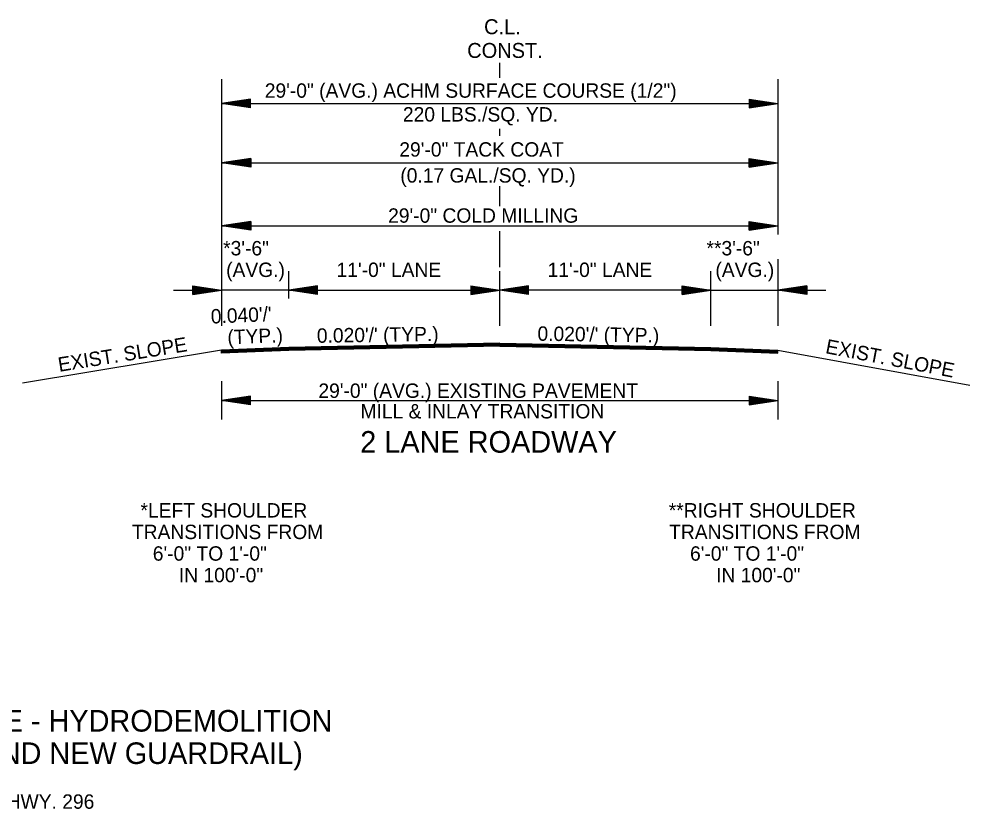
# Model space of a CAD drawing. Extents: x 542112 to 1930787, y -1968972 to 596640.
# Drawn here: x 544741.8 to 545237.5, y -1962582 to -1962170.3 of the extents above; entities that cross this region are included whole.
import ezdxf

# ---------------------------------------------------------------- set-up
doc = ezdxf.new("R2010")
doc.units = 0
doc.layers.add('R_Draft', color=7, linetype='Continuous')

msp = doc.modelspace()

# ---------------------------------------------------------------- linework, layer by layer
at = {"layer": 'R_Draft'}
for p, q in [((544992.39, -1962200.98), (544992.39, -1962193.12)), ((544847.39, -1962201.56), (544847.39, -1962330.24)), ((545137.39, -1962201.56), (545137.39, -1962282.57)), ((544862.39, -1962212.07), (544847.39, -1962214.32)), ((544847.39, -1962214.32), (545137.39, -1962214.32)), ((544862.39, -1962216.57), (544847.39, -1962214.32)), ((544862.39, -1962212.44), (544849.89, -1962214.32)), ((544862.39, -1962216.19), (544849.89, -1962214.32)), ((544862.39, -1962212.83), (544852.47, -1962214.32)), ((544862.39, -1962215.81), (544852.47, -1962214.32)), ((544862.39, -1962213.2), (544854.97, -1962214.32)), ((544862.39, -1962215.44), (544854.97, -1962214.32)), ((544862.39, -1962213.58), (544857.51, -1962214.32)), ((544862.39, -1962215.05), (544857.51, -1962214.32)), ((544862.39, -1962213.97), (544860.02, -1962214.32)), ((544862.39, -1962214.67), (544860.02, -1962214.32)), ((544862.39, -1962216.57), (544862.39, -1962212.07)), ((545122.39, -1962212.07), (545137.39, -1962214.32)), ((545122.39, -1962212.07), (545122.39, -1962216.57)), ((545122.39, -1962212.44), (545134.88, -1962214.32)), ((545122.39, -1962212.83), (545132.3, -1962214.32)), ((545122.39, -1962213.2), (545129.81, -1962214.32)), ((545122.39, -1962213.59), (545127.26, -1962214.32)), ((545122.39, -1962213.97), (545124.76, -1962214.32)), ((545122.39, -1962216.57), (545137.39, -1962214.32)), ((545122.39, -1962215.05), (545127.26, -1962214.32)), ((545122.39, -1962215.81), (545132.3, -1962214.32)), ((545122.39, -1962216.19), (545134.88, -1962214.32)), ((545122.39, -1962215.44), (545129.81, -1962214.32)), ((545122.39, -1962214.67), (545124.76, -1962214.32)), ((544992.39, -1962231.1), (544992.39, -1962227.43)), ((544847.39, -1962245.19), (545137.39, -1962245.19)), ((544862.59, -1962242.94), (544847.59, -1962245.19)), ((544862.59, -1962247.44), (544847.59, -1962245.19)), ((544862.59, -1962243.31), (544850.09, -1962245.19)), ((544862.59, -1962247.06), (544850.09, -1962245.19)), ((544862.59, -1962243.7), (544852.67, -1962245.19)), ((544862.59, -1962246.68), (544852.67, -1962245.19)), ((544862.59, -1962244.07), (544855.17, -1962245.19)), ((544862.59, -1962246.31), (544855.17, -1962245.19)), ((544862.59, -1962244.46), (544857.71, -1962245.19)), ((544862.59, -1962245.92), (544857.71, -1962245.19)), ((544862.59, -1962244.84), (544860.22, -1962245.19)), ((544862.59, -1962245.54), (544860.22, -1962245.19)), ((544862.59, -1962242.94), (544862.59, -1962247.44)), ((545122.39, -1962242.94), (545137.39, -1962245.19)), ((545122.39, -1962247.44), (545122.39, -1962242.94)), ((545122.39, -1962243.31), (545134.88, -1962245.19)), ((545122.39, -1962243.7), (545132.3, -1962245.19)), ((545122.39, -1962244.07), (545129.81, -1962245.19)), ((545122.39, -1962244.45), (545127.26, -1962245.19)), ((545122.39, -1962244.84), (545124.76, -1962245.19)), ((545122.39, -1962247.44), (545137.39, -1962245.19)), ((545122.39, -1962245.92), (545127.26, -1962245.19)), ((545122.39, -1962246.68), (545132.3, -1962245.19)), ((545122.39, -1962247.06), (545134.88, -1962245.19)), ((545122.39, -1962246.31), (545129.81, -1962245.19)), ((545122.39, -1962245.54), (545124.76, -1962245.19)), ((544992.39, -1962267.86), (544992.39, -1962257.34)), ((544847.39, -1962278.12), (545137.39, -1962278.12)), ((544862.59, -1962275.87), (544847.59, -1962278.12)), ((544862.59, -1962280.37), (544847.59, -1962278.12)), ((544862.59, -1962276.24), (544850.09, -1962278.12)), ((544862.59, -1962279.99), (544850.09, -1962278.12)), ((544862.59, -1962276.63), (544852.67, -1962278.12)), ((544862.59, -1962279.61), (544852.67, -1962278.12)), ((544862.59, -1962277), (544855.17, -1962278.12)), ((544862.59, -1962279.24), (544855.17, -1962278.12)), ((544862.59, -1962277.39), (544857.71, -1962278.12)), ((544862.59, -1962278.85), (544857.71, -1962278.12)), ((544862.59, -1962277.77), (544860.22, -1962278.12)), ((544862.59, -1962278.47), (544860.22, -1962278.12)), ((544862.59, -1962275.87), (544862.59, -1962280.37)), ((545122.39, -1962275.87), (545137.39, -1962278.12)), ((545122.39, -1962280.37), (545122.39, -1962275.87)), ((545122.39, -1962276.24), (545134.88, -1962278.12)), ((545122.39, -1962276.63), (545132.3, -1962278.12)), ((545122.39, -1962277), (545129.81, -1962278.12)), ((545122.39, -1962277.38), (545127.26, -1962278.12)), ((545122.39, -1962277.77), (545124.76, -1962278.12)), ((545122.39, -1962280.37), (545137.39, -1962278.12)), ((545122.39, -1962278.85), (545127.26, -1962278.12)), ((545122.39, -1962279.61), (545132.3, -1962278.12)), ((545122.39, -1962279.99), (545134.88, -1962278.12)), ((545122.39, -1962279.24), (545129.81, -1962278.12)), ((545122.39, -1962278.47), (545124.76, -1962278.12)), ((544992.39, -1962299.57), (544992.39, -1962280.87)), ((545137.39, -1962295.37), (545137.39, -1962330.24)), ((544882.39, -1962315.97), (544882.39, -1962301.69)), ((544992.39, -1962330.24), (544992.39, -1962301.69)), ((545102.39, -1962330.24), (545102.39, -1962301.69)), ((544832.39, -1962309.33), (544847.39, -1962311.58)), ((544832.39, -1962313.83), (544832.39, -1962309.33)), ((544832.39, -1962309.71), (544844.88, -1962311.58)), ((544832.39, -1962310.09), (544842.3, -1962311.58)), ((544897.39, -1962309.33), (544882.39, -1962311.58)), ((544897.39, -1962309.71), (544884.89, -1962311.58)), ((544897.39, -1962310.09), (544887.47, -1962311.58)), ((544897.39, -1962313.83), (544897.39, -1962309.33)), ((544977.39, -1962309.33), (544992.39, -1962311.58)), ((544977.39, -1962309.33), (544977.39, -1962313.83)), ((544977.39, -1962309.71), (544989.88, -1962311.58)), ((544977.39, -1962310.09), (544987.3, -1962311.58)), ((545007.39, -1962309.33), (544992.39, -1962311.58)), ((545007.39, -1962309.71), (544994.89, -1962311.58)), ((545007.39, -1962310.09), (544997.47, -1962311.58)), ((545007.39, -1962313.83), (545007.39, -1962309.33)), ((545087.39, -1962309.33), (545102.39, -1962311.58)), ((545087.39, -1962313.83), (545087.39, -1962309.33)), ((545087.39, -1962309.71), (545099.88, -1962311.58)), ((545087.39, -1962310.09), (545097.3, -1962311.58)), ((545152.39, -1962309.33), (545137.39, -1962311.58)), ((545152.39, -1962309.71), (545139.89, -1962311.58)), ((545152.39, -1962310.09), (545142.47, -1962311.58)), ((545152.39, -1962309.33), (545152.39, -1962313.83)), ((544822.39, -1962311.58), (544847.39, -1962311.58)), ((544832.39, -1962310.47), (544839.81, -1962311.58)), ((544832.39, -1962310.85), (544837.26, -1962311.58)), ((544832.39, -1962311.23), (544834.76, -1962311.58)), ((544832.39, -1962313.83), (544847.39, -1962311.58)), ((544832.39, -1962312.31), (544837.26, -1962311.58)), ((544832.39, -1962313.08), (544842.3, -1962311.58)), ((544832.39, -1962313.46), (544844.88, -1962311.58)), ((544832.39, -1962312.7), (544839.81, -1962311.58)), ((544832.39, -1962311.94), (544834.76, -1962311.58)), ((544882.39, -1962311.58), (544847.39, -1962311.58)), ((544897.39, -1962313.83), (544882.39, -1962311.58)), ((544882.39, -1962311.58), (544992.39, -1962311.58)), ((544897.39, -1962313.46), (544884.89, -1962311.58)), ((544897.39, -1962313.08), (544887.47, -1962311.58)), ((544897.39, -1962310.47), (544889.97, -1962311.58)), ((544897.39, -1962312.7), (544889.97, -1962311.58)), ((544897.39, -1962310.85), (544892.51, -1962311.58)), ((544897.39, -1962312.31), (544892.51, -1962311.58)), ((544897.39, -1962311.23), (544895.02, -1962311.58)), ((544897.39, -1962311.94), (544895.02, -1962311.58)), ((544977.39, -1962310.47), (544984.81, -1962311.58)), ((544977.39, -1962310.86), (544982.26, -1962311.58)), ((544977.39, -1962311.23), (544979.76, -1962311.58)), ((544977.39, -1962313.83), (544992.39, -1962311.58)), ((544977.39, -1962312.32), (544982.26, -1962311.58)), ((544977.39, -1962313.08), (544987.3, -1962311.58)), ((544977.39, -1962313.46), (544989.88, -1962311.58)), ((544977.39, -1962312.7), (544984.81, -1962311.58)), ((544977.39, -1962311.94), (544979.76, -1962311.58)), ((545102.39, -1962311.58), (544992.39, -1962311.58)), ((545007.39, -1962313.83), (544992.39, -1962311.58)), ((545007.39, -1962313.46), (544994.89, -1962311.58)), ((545007.39, -1962313.08), (544997.47, -1962311.58)), ((545007.39, -1962310.47), (544999.97, -1962311.58)), ((545007.39, -1962312.7), (544999.97, -1962311.58)), ((545007.39, -1962310.85), (545002.51, -1962311.58)), ((545007.39, -1962312.31), (545002.51, -1962311.58)), ((545007.39, -1962311.23), (545005.02, -1962311.58)), ((545007.39, -1962311.94), (545005.02, -1962311.58)), ((545087.39, -1962310.47), (545094.81, -1962311.58)), ((545087.39, -1962310.85), (545092.26, -1962311.58)), ((545087.39, -1962311.23), (545089.76, -1962311.58)), ((545087.39, -1962313.83), (545102.39, -1962311.58)), ((545087.39, -1962312.31), (545092.26, -1962311.58)), ((545087.39, -1962313.08), (545097.3, -1962311.58)), ((545087.39, -1962313.46), (545099.88, -1962311.58)), ((545087.39, -1962312.7), (545094.81, -1962311.58)), ((545087.39, -1962311.94), (545089.76, -1962311.58)), ((545102.39, -1962311.58), (545137.39, -1962311.58)), ((545152.39, -1962313.83), (545137.39, -1962311.58)), ((545137.39, -1962311.58), (545162.39, -1962311.58)), ((545152.39, -1962313.46), (545139.89, -1962311.58)), ((545152.39, -1962313.08), (545142.47, -1962311.58)), ((545152.39, -1962310.47), (545144.97, -1962311.58)), ((545152.39, -1962312.7), (545144.97, -1962311.58)), ((545152.39, -1962310.86), (545147.51, -1962311.58)), ((545152.39, -1962312.32), (545147.51, -1962311.58)), ((545152.39, -1962311.23), (545150.02, -1962311.58)), ((545152.39, -1962311.94), (545150.02, -1962311.58)), ((544992.39, -1962339.19), (544882.39, -1962341.39)), ((544992.39, -1962339.49), (544882.39, -1962341.69)), ((544992.4, -1962339.79), (544882.39, -1962341.99)), ((544992.41, -1962340.09), (544882.39, -1962342.29)), ((544992.37, -1962340.09), (545102.39, -1962342.29)), ((544992.38, -1962339.49), (545102.39, -1962341.69)), ((544992.38, -1962339.79), (545102.39, -1962341.99)), ((544992.39, -1962339.19), (545102.39, -1962341.39)), ((544847.39, -1962342.79), (544743.7, -1962360.07)), ((544882.39, -1962341.39), (544847.39, -1962342.79)), ((544882.39, -1962341.69), (544847.39, -1962343.09)), ((544882.39, -1962341.99), (544847.39, -1962343.39)), ((544882.39, -1962342.29), (544847.39, -1962343.69)), ((544882.39, -1962342.59), (544847.39, -1962343.99)), ((544847.39, -1962344.46), (544847.39, -1962342.79)), ((544882.39, -1962342.89), (544847.39, -1962344.29)), ((544882.39, -1962343.06), (544847.39, -1962344.46)), ((544992.41, -1962340.39), (544882.39, -1962342.59)), ((544992.42, -1962340.69), (544882.39, -1962342.89)), ((544992.42, -1962340.86), (544882.39, -1962343.06)), ((544992.35, -1962340.86), (545102.39, -1962343.06)), ((544992.36, -1962340.39), (545102.39, -1962342.59)), ((544992.36, -1962340.69), (545102.39, -1962342.89)), ((545102.39, -1962341.39), (545137.39, -1962342.79)), ((545102.39, -1962341.69), (545137.39, -1962343.09)), ((545102.39, -1962341.99), (545137.39, -1962343.39)), ((545102.39, -1962342.29), (545137.39, -1962343.69)), ((545102.39, -1962342.59), (545137.39, -1962343.99)), ((545102.39, -1962342.89), (545137.39, -1962344.29)), ((545102.39, -1962343.06), (545137.39, -1962344.46)), ((545137.39, -1962342.79), (545237.46, -1962361.17)), ((545137.39, -1962344.46), (545137.39, -1962342.79)), ((544847.39, -1962359.05), (544847.39, -1962379.05)), ((545137.39, -1962359.05), (545137.39, -1962379.05)), ((544862.39, -1962366.8), (544847.39, -1962369.05)), ((544847.39, -1962369.05), (545137.39, -1962369.05)), ((544862.39, -1962371.3), (544847.39, -1962369.05)), ((544862.39, -1962367.17), (544849.89, -1962369.05)), ((544862.39, -1962370.92), (544849.89, -1962369.05)), ((544862.39, -1962367.56), (544852.47, -1962369.05)), ((544862.39, -1962370.54), (544852.47, -1962369.05)), ((544862.39, -1962367.93), (544854.97, -1962369.05)), ((544862.39, -1962370.17), (544854.97, -1962369.05)), ((544862.39, -1962368.31), (544857.51, -1962369.05)), ((544862.39, -1962369.78), (544857.51, -1962369.05)), ((544862.39, -1962368.7), (544860.02, -1962369.05)), ((544862.39, -1962369.4), (544860.02, -1962369.05)), ((544862.39, -1962371.3), (544862.39, -1962366.8)), ((545122.39, -1962366.8), (545137.39, -1962369.05)), ((545122.39, -1962366.8), (545122.39, -1962371.3)), ((545122.39, -1962367.17), (545134.88, -1962369.05)), ((545122.39, -1962367.56), (545132.3, -1962369.05)), ((545122.39, -1962367.93), (545129.81, -1962369.05)), ((545122.39, -1962368.32), (545127.26, -1962369.05)), ((545122.39, -1962368.7), (545124.76, -1962369.05)), ((545122.39, -1962371.3), (545137.39, -1962369.05)), ((545122.39, -1962369.78), (545127.26, -1962369.05)), ((545122.39, -1962370.54), (545132.3, -1962369.05)), ((545122.39, -1962370.92), (545134.88, -1962369.05)), ((545122.39, -1962370.17), (545129.81, -1962369.05)), ((545122.39, -1962369.4), (545124.76, -1962369.05))]:
    msp.add_line(p, q, dxfattribs=at)

# ---------------------------------------------------------------- texts
for s, height, p in [('C.L.', 7.8, (544984.21, -1962178.18)), ('CONST.', 7.8, (544975.42, -1962190.55)), ('29\'-0" (AVG.) ACHM SURFACE COURSE (1/2")', 7.5, (544869.91, -1962211.3)), ('220 LBS./SQ. YD. ', 7.5, (544941.9, -1962223.7)), ('29\'-0" TACK COAT', 7.5, (544940.04, -1962241.99)), ('(0.17 GAL./SQ. YD.)', 7.5, (544940.54, -1962255.53)), ('29\'-0" COLD MILLING', 7.5, (544934.19, -1962276.45)), ('*3\'-6"', 7.5, (544848.2, -1962293.47)), ('**3\'-6"', 7.5, (545100.13, -1962293.47)), ('(AVG.)', 7.5, (544849.77, -1962304.72)), ('11\'-0" LANE', 7.5, (544907.33, -1962304.72)), ('11\'-0" LANE', 7.5, (545017.33, -1962304.72)), ('(AVG.)', 7.5, (545104.77, -1962304.72)), ('29\'-0" (AVG.) EXISTING PAVEMENT', 7.5, (544897.87, -1962367.73)), ('MILL & INLAY TRANSITION', 7.5, (544919.78, -1962378.45)), ('2 LANE ROADWAY', 11.25, (544919.66, -1962396.29)), ('*LEFT SHOULDER', 7.5, (544805.11, -1962430.09)), ('**RIGHT SHOULDER', 7.5, (545080.45, -1962430.09)), ('TRANSITIONS FROM', 7.5, (544800.66, -1962441.34)), ('TRANSITIONS FROM', 7.5, (545080.66, -1962441.34)), ('6\'-0" TO 1\'-0"', 7.5, (544811.55, -1962452.59)), ('6\'-0" TO 1\'-0" ', 7.5, (545091.55, -1962452.59)), ('IN 100\'-0" ', 7.5, (544825.13, -1962463.84)), ('IN 100\'-0"', 7.5, (545105.13, -1962463.84)), ('24 FT. CLEAR ROADWAY BRIDGE - HYDRODEMOLITION', 11.25, (544502.24, -1962541.67)), ('(ROADWAY TRANSITIONS AND NEW GUARDRAIL)', 11.25, (544529.48, -1962558.55)), ('19 - BR. NO. 03568 - HWY. 296', 7.5, (544638.39, -1962581.9))]:
    msp.add_text(s, height=height, dxfattribs=at).set_placement(p)
for s, rotation, p in [("  0.040'/'", 2.448, (544836.36, -1962329.27)), ("0.020'/' (TYP.)", 0.8719, (544897.11, -1962339.05)), (' (TYP.)', 2.448, (544847.79, -1962340.04)), ("0.020'/' (TYP.)", 359.1281, (545011.99, -1962337.92)), ('EXIST. SLOPE', 9.1534, (544762.78, -1962354.18)), ('EXIST. SLOPE', 349.1171, (545161.77, -1962344.39))]:
    msp.add_text(s, height=7.5, rotation=rotation, dxfattribs=at).set_placement(p)

doc.saveas('drawing.dxf')
